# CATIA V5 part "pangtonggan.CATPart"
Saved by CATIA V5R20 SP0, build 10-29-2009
Part number: pangtonggan
Material "无"
Bounding box of the stored display mesh (mm): x 33.458 to 106.36, y -28.408 to 14.01, z -113.682 to -99
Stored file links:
  C:\Users\Administrator\Desktop\pangtonggan.CATPart
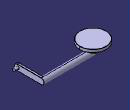
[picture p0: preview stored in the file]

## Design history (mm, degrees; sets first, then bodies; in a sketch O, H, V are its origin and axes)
Body1 (main body), material "无"
  DatumSurface1
  DatumCurve1
  Sketch1 on face of DatumSurface1, origin (0, 0, -99), H (1, 0, 0), V (0, 1, 0)
    projected circle E1 centre (47.4681, 0) radius 14.0099 from edge of DatumCurve1
  Pad1: profile Sketch1, direction (0, 0, -1), length 4
  Fillet1: radius 1, on end face of Pad1
  Fillet2: radius 0.2, on edge [face of Pad1 from Sketch1.E1 | start face of Pad1]
  Sketch2 on end face of Pad1, origin (0, 0, -103), H (1, 0, 0), V (0, -1, 0)
    circle A1 centre (48.1177, 0) radius 3.113
    point P1 (48.1177, 0)
    coincidence: P1 H
  Sketch3 on zx-plane, origin (0, 0, 0), H (-1, 0, 0), V (0, 0, 1)
    line L1 (-48.549, -103.0197) -> (-48.549, -110.1375)
    line L2 (-48.549, -110.1375) -> (-100.3792, -110.1375)
    vertical: L1 V
    horizontal: L2 H
  Rib1: profile Sketch2, centre curve Sketch3
  Sketch4 on face of Rib1, origin (100.3595, 0, 0), H (0, 1, 0), V (0, 0, 1)
    projected circle E1 centre (0, -110.5687) radius 3.113 from face of Rib1
    projected arc E2 centre (0, -110.5687) radius 3.113 from (0, -113.6817) to (0, -107.4558) ccw from face of Rib1
    arc A1 centre (-25.4475, -110.5687) radius 3.113 from (-25.4475, -107.4558) to (-25.4475, -113.6817) ccw
    line L1 (-25.4475, -107.4558) -> (0, -107.4558)
    line L2 (0, -113.6817) -> (-25.4475, -113.6817)
    point P3 (0, -113.6817)
    point P4 (0, -107.4558)
    tangency: L1 A1, L2 A1, L1 E1, L2 E1
    coincidence: P3 V, P3 E1, E1 P4
  Pad2: profile Sketch4, direction (1, 0, 0), length 2
  Fillet3: radius 0.2, on end face of Pad2
  Sketch5 on end face of Pad2, origin (102.3595, 0, 0), H (0, 1, 0), V (0, 0, 1)
    circle A1 centre (-24.7747, -110.5426) radius 1.5283
  Pad3: profile Sketch5, direction (1, 0, 0), length 4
